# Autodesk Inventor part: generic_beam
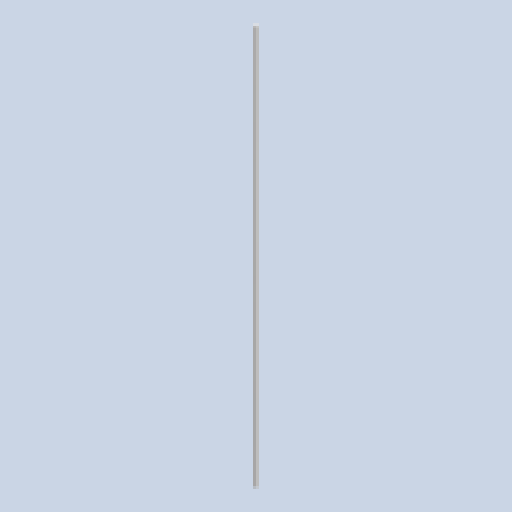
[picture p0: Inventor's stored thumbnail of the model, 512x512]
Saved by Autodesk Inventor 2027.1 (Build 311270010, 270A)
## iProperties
Created: 2026-07
Part Number: generic_beam
Material: Generic
Document SubType Name: Modeling
Designer: dunge
Density: 1 g/cm^3
Appearance: Default
Author: dunge
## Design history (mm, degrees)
sketch "Sketch1"
  geometry: L1 (-9.64, 0.476)-(-10.91, 0.476); L2 (-10.91, 0.476)-(-10.91, -0.794); L3 (-10.91, -0.794)-(-9.64, -0.794); L4 (-9.64, -0.794)-(-9.64, 0.476); C1 r 0.635 at (-10.275, -0.159); 1 further point
  constraints: 8 end point, 2 parallel, 1 centre point, 1 horizontal, 1 perpendicular
  dimensions: "d0" = 1.27 distance of L1.end L2.end; "d1" = 1.27 distance of L2.end L3.end
extrude "Extrusion1" new body sketch "Sketch1" distance "d2" = 254; taper "d3" = 0 deg
sketch "Sketch2"
  geometry: C1 r 0.635 at (0, 0); 1 further point
  constraints: 1 centre point
extrude "Extrusion2" cut sketch "Sketch2" distance "d4" = 111.125; taper "d5" = 0 deg
body "Solid1"
